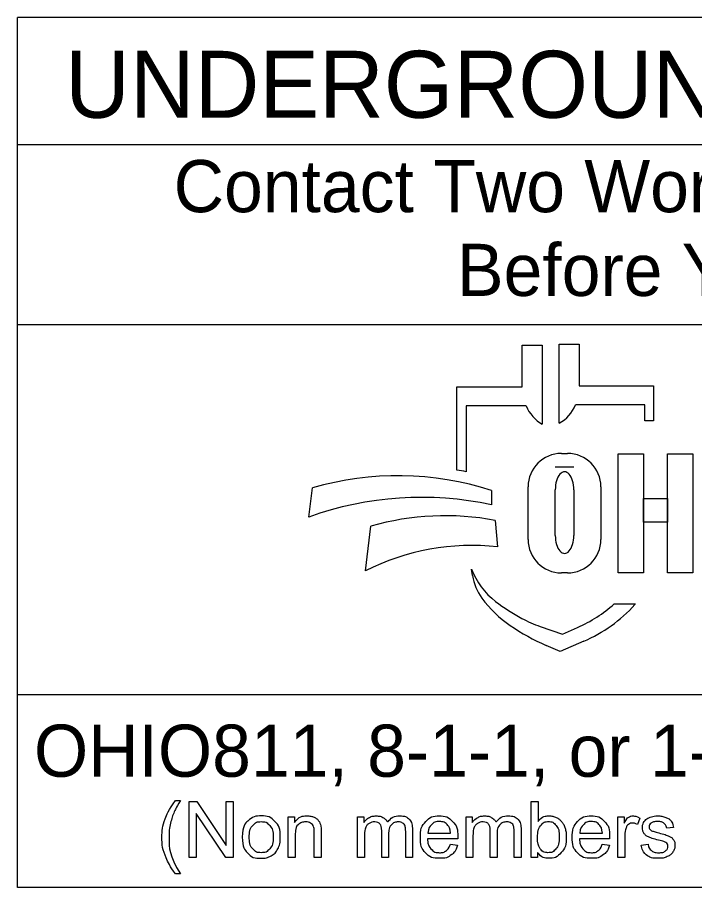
# Model space of a CAD drawing. Extents: x -10.1 to 68, y -9.5 to 29.2.
# Drawn here: x 2.978 to 4.796, y 2.143 to 4.48 of the extents above; entities that cross this region are included whole.
import ezdxf

# ---------------------------------------------------------------- set-up
doc = ezdxf.new("R2010")
doc.units = 0
doc.layers.add('SH_Data', color=7, linetype='Continuous')
doc.layers.add('SH_Text', color=7, linetype='Continuous')

msp = doc.modelspace()

# ---------------------------------------------------------------- linework, layer by layer
at = {"layer": 'SH_Data'}
for p, q in [((2.9775, 2.1428), (2.9775, 4.4803)), ((7.2275, 4.4803), (2.9775, 4.4803)), ((2.9775, 4.1387), (7.2275, 4.1387)), ((2.9775, 3.6553), (7.2275, 3.6553)), ((7.2275, 2.6607), (2.9775, 2.6607)), ((7.2275, 2.1428), (2.9775, 2.1428))]:
    msp.add_line(p, q, dxfattribs=at)
at = {"layer": 'SH_Text'}
for p, q in [((4.3335, 3.4883), (4.3335, 3.5998)), ((4.3335, 3.5998), (4.3872, 3.5998)), ((4.3872, 3.5998), (4.3872, 3.3877)), ((4.4329, 3.39), (4.4329, 3.6021)), ((4.4329, 3.6021), (4.4865, 3.6021)), ((4.4865, 3.6021), (4.4865, 3.4906)), ((4.1576, 3.2644), (4.1576, 3.4883)), ((4.1576, 3.4883), (4.3335, 3.4883)), ((4.4865, 3.4906), (4.6857, 3.4906)), ((4.6857, 3.4906), (4.6857, 3.3968)), ((4.1828, 3.4369), (4.1828, 3.26)), ((4.3439, 3.4369), (4.1828, 3.4369)), ((4.6625, 3.4392), (4.4761, 3.4392)), ((4.6625, 3.3968), (4.6625, 3.4392)), ((4.6857, 3.3968), (4.6625, 3.3968)), ((4.4385, 3.3091), (4.4551, 3.3091)), ((4.4718, 3.2721), (4.422, 3.2721)), ((3.7602, 3.1381), (3.7696, 3.2162)), ((4.2509, 3.2097), (4.2509, 3.1709)), ((4.3491, 3.0776), (4.3491, 3.2196)), ((4.422, 3.089), (4.422, 3.2114)), ((4.4718, 3.2114), (4.4718, 3.089)), ((4.5445, 3.2196), (4.5445, 3.0776)), ((3.912, 2.9936), (3.9267, 3.1137)), ((4.2608, 3.1291), (4.2671, 3.0582)), ((4.1997, 2.9807), (4.1967, 2.9986)), ((4.4551, 2.9882), (4.4385, 2.9882)), ((4.58, 2.9048), (4.6375, 2.9048)), ((4.3816, 2.8444), (4.441, 2.8239)), ((4.441, 2.8239), (4.4821, 2.8417)), ((4.435, 2.7769), (4.3976, 2.7934)), ((4.4983, 2.8044), (4.435, 2.7769))]:
    msp.add_line(p, q, dxfattribs=at)
for points in [[(4.591, 3.3081), (4.6589, 3.3081), (4.6589, 2.9881), (4.591, 2.9881)], [(4.7231, 3.3081), (4.7911, 3.3081), (4.7911, 2.9881), (4.7231, 2.9881)], [(4.6589, 3.1882), (4.7231, 3.1882), (4.7231, 3.1242), (4.6589, 3.1242)]]:
    msp.add_lwpolyline(points, close=True, dxfattribs=at)
for points in [[(3.4021, 2.3766), (3.4153, 2.3766)], [(3.4389, 2.2239), (3.4389, 2.3741), (3.4592, 2.3741), (3.5382, 2.2561), (3.5382, 2.3741), (3.5572, 2.3741), (3.5572, 2.2239), (3.5369, 2.2239), (3.4579, 2.3419), (3.4579, 2.2239), (3.4389, 2.2239)], [(4.3743, 2.2239), (4.3573, 2.2239), (4.3573, 2.3741), (4.3757, 2.3741), (4.3757, 2.3206)], [(3.7048, 2.2239), (3.7048, 2.3328), (3.7214, 2.3328), (3.7214, 2.3173)], [(3.8912, 2.2239), (3.8912, 2.3328), (3.9077, 2.3328), (3.9077, 2.3174)], [(4.1826, 2.2239), (4.1826, 2.3328), (4.1991, 2.3328), (4.1991, 2.3174)], [(4.5904, 2.2239), (4.5904, 2.3328), (4.607, 2.3328), (4.607, 2.3163)], [(4.6495, 2.3293), (4.643, 2.3122)], [(3.7932, 2.2908), (3.7932, 2.2239), (3.7748, 2.2239), (3.7748, 2.2901)], [(3.9743, 2.2871), (3.9743, 2.2239), (3.9559, 2.2239), (3.9559, 2.2946)], [(4.0388, 2.2986), (4.0388, 2.2239), (4.0203, 2.2239), (4.0203, 2.2924)], [(4.2657, 2.2871), (4.2657, 2.2239), (4.2473, 2.2239), (4.2473, 2.2946)], [(4.3301, 2.2986), (4.3301, 2.2239), (4.3117, 2.2239), (4.3117, 2.2924)], [(4.7394, 2.3046), (4.7213, 2.3022)], [(3.7233, 2.2833), (3.7233, 2.2239), (3.7048, 2.2239)], [(3.9097, 2.2803), (3.9097, 2.2239), (3.8912, 2.2239)], [(4.16, 2.2736), (4.0788, 2.2736)], [(4.0799, 2.2887), (4.1406, 2.2887)], [(4.201, 2.2803), (4.201, 2.2239), (4.1826, 2.2239)], [(4.568, 2.2736), (4.4868, 2.2736)], [(4.4879, 2.2887), (4.5486, 2.2887)], [(4.6088, 2.2809), (4.6088, 2.2239), (4.5904, 2.2239)], [(4.1404, 2.2591), (4.1595, 2.2567)], [(4.5484, 2.2591), (4.5675, 2.2567)], [(4.653, 2.2564), (4.6712, 2.2593)], [(4.3743, 2.2375), (4.3743, 2.2239)], [(3.4153, 2.1798), (3.4021, 2.1798)]]:
    msp.add_lwpolyline(points, dxfattribs=at)
for centre, radius, start, end in [((4.4353, 3.4736), 0.0985, 201.9296, 240.7469), ((4.3847, 3.476), 0.0985, 299.2531, 338.0704), ((4.4385, 3.2196), 0.0895, 90, 180), ((4.4551, 3.2196), 0.0895, 0, 90), ((3.9997, 2.4302), 0.8191, 72.1402, 106.3144), ((4.0295, 2.4554), 0.8191, 79.2074, 81.0007), ((4.0628, 2.2991), 0.8919, 77.8238, 109.8274), ((4.1267, 2.4094), 0.7322, 79.44, 105.8467), ((4.4385, 3.0776), 0.0895, 180, 270), ((4.4551, 3.0776), 0.0895, 270, 0), ((4.1987, 2.4262), 0.6357, 83.8248, 116.8021), ((4.3841, 3.0707), 0.2008, 201.0457, 232.5314), ((4.341, 3.0048), 0.1433, 189.6817, 216.0884), ((4.4747, 3.1022), 0.3088, 216.0884, 235.7167), ((4.5766, 3.3219), 0.5173, 232.5314, 241.794), ((4.3387, 3.1722), 0.3602, 293.4582, 312.0712), ((4.3387, 3.1722), 0.401, 293.4582, 317.8286), ((4.4914, 3.1631), 0.3371, 241.794, 250.9821), ((4.6412, 3.3465), 0.6044, 235.7167, 246.2325)]:
    msp.add_arc(centre, radius, start, end, dxfattribs=at)
for centre, start_param, end_param in [((4.4469, 3.2114), 4.712389, 7.853982), ((4.4469, 3.089), 1.570796, 4.712389)]:
    msp.add_ellipse(centre, major_axis=(0, 0.0484), ratio=0.514403, start_param=start_param, end_param=end_param, dxfattribs=at)
for points in [[(3.4021, 2.1798), (3.3869, 2.199), (3.3763, 2.2248), (3.3657, 2.2506), (3.3657, 2.2783), (3.3657, 2.3026), (3.3736, 2.325), (3.3829, 2.3509), (3.4021, 2.3766)], [(3.4153, 2.3766), (3.4029, 2.3553), (3.3989, 2.3462), (3.3927, 2.332), (3.3891, 2.3167), (3.3847, 2.2975), (3.3847, 2.2782), (3.3847, 2.2289), (3.4153, 2.1798)], [(3.5814, 2.2783), (3.5814, 2.3085), (3.5981, 2.3231), (3.6122, 2.3352), (3.6323, 2.3352), (3.6547, 2.3352), (3.669, 2.3205), (3.6832, 2.3058), (3.6832, 2.2799), (3.6832, 2.2589), (3.6769, 2.2469), (3.6706, 2.2348), (3.6586, 2.2282), (3.6466, 2.2215), (3.6323, 2.2215), (3.6095, 2.2215), (3.5954, 2.2362), (3.5814, 2.2508), (3.5814, 2.2783)], [(3.6003, 2.2783), (3.6003, 2.2574), (3.6094, 2.247), (3.6185, 2.2366), (3.6323, 2.2366), (3.646, 2.2366), (3.6551, 2.2471), (3.6642, 2.2575), (3.6642, 2.279), (3.6642, 2.2991), (3.6551, 2.3095), (3.6459, 2.3199), (3.6323, 2.3199), (3.6185, 2.3199), (3.6094, 2.3096), (3.6003, 2.2992), (3.6003, 2.2783)], [(3.7214, 2.3173), (3.7334, 2.3352), (3.756, 2.3352), (3.7659, 2.3352), (3.7741, 2.3316), (3.7823, 2.3281), (3.7864, 2.3224), (3.7905, 2.3166), (3.7922, 2.3087), (3.7932, 2.3036), (3.7932, 2.2908)], [(3.7748, 2.2901), (3.7748, 2.3013), (3.7726, 2.3069), (3.7705, 2.3125), (3.765, 2.3158), (3.7595, 2.3191), (3.7521, 2.3191), (3.7404, 2.3191), (3.7318, 2.3117), (3.7233, 2.3042), (3.7233, 2.2833)], [(3.9077, 2.3174), (3.9128, 2.3254), (3.9214, 2.3303), (3.9299, 2.3352), (3.9407, 2.3352), (3.9528, 2.3352), (3.9606, 2.3301), (3.9683, 2.3251), (3.9715, 2.3161), (3.9844, 2.3352), (4.0051, 2.3352), (4.0213, 2.3352), (4.03, 2.3262), (4.0388, 2.3172), (4.0388, 2.2986)], [(3.9559, 2.2946), (3.9559, 2.3069), (3.9514, 2.313), (3.9469, 2.3191), (3.9366, 2.3191), (3.9288, 2.3191), (3.9222, 2.315), (3.9156, 2.311), (3.9126, 2.3031), (3.9097, 2.2952), (3.9097, 2.2803)], [(4.0203, 2.2924), (4.0203, 2.3035), (4.0185, 2.3083), (4.0168, 2.3132), (4.012, 2.3162), (4.0073, 2.3191), (4.001, 2.3191), (3.9895, 2.3191), (3.9819, 2.3115), (3.9743, 2.3039), (3.9743, 2.2871)], [(4.1595, 2.2567), (4.155, 2.24), (4.1428, 2.2307), (4.1306, 2.2215), (4.1117, 2.2215), (4.0878, 2.2215), (4.0738, 2.2362), (4.0598, 2.2509), (4.0598, 2.2774), (4.0598, 2.3049), (4.074, 2.32), (4.0881, 2.3352), (4.1106, 2.3352), (4.1324, 2.3352), (4.1463, 2.3203), (4.1601, 2.3055), (4.1601, 2.2785), (4.1601, 2.2769), (4.16, 2.2736)], [(4.1406, 2.2887), (4.1394, 2.3025), (4.1337, 2.3094), (4.1249, 2.3201), (4.1108, 2.3201), (4.0981, 2.3201), (4.0894, 2.3115), (4.0808, 2.303), (4.0799, 2.2887)], [(4.1991, 2.3174), (4.2042, 2.3254), (4.2127, 2.3303), (4.2212, 2.3352), (4.2321, 2.3352), (4.2442, 2.3352), (4.2519, 2.3301), (4.2597, 2.3251), (4.2628, 2.3161), (4.2758, 2.3352), (4.2965, 2.3352), (4.3127, 2.3352), (4.3214, 2.3262), (4.3301, 2.3172), (4.3301, 2.2986)], [(4.2473, 2.2946), (4.2473, 2.3069), (4.2428, 2.313), (4.2383, 2.3191), (4.228, 2.3191), (4.2202, 2.3191), (4.2136, 2.315), (4.207, 2.311), (4.204, 2.3031), (4.201, 2.2952), (4.201, 2.2803)], [(4.3117, 2.2924), (4.3117, 2.3035), (4.3099, 2.3083), (4.3081, 2.3132), (4.3034, 2.3162), (4.2987, 2.3191), (4.2923, 2.3191), (4.2809, 2.3191), (4.2733, 2.3115), (4.2657, 2.3039), (4.2657, 2.2871)], [(4.3741, 2.2792), (4.3741, 2.2596), (4.3794, 2.2509), (4.3881, 2.2366), (4.4029, 2.2366), (4.415, 2.2366), (4.4238, 2.2471), (4.4326, 2.2576), (4.4326, 2.2784), (4.4326, 2.2998), (4.4241, 2.3099), (4.4157, 2.3201), (4.4038, 2.3201), (4.3917, 2.3201), (4.3829, 2.3096), (4.3741, 2.299), (4.3741, 2.2792)], [(4.3757, 2.3206), (4.3874, 2.3352), (4.4055, 2.3352), (4.4155, 2.3352), (4.4245, 2.3311), (4.4335, 2.3271), (4.4392, 2.3198), (4.445, 2.3124), (4.4483, 2.3021), (4.4516, 2.2918), (4.4516, 2.28), (4.4516, 2.252), (4.4378, 2.2368), (4.4239, 2.2215), (4.4046, 2.2215), (4.3853, 2.2215), (4.3743, 2.2375)], [(4.5675, 2.2567), (4.563, 2.24), (4.5508, 2.2307), (4.5386, 2.2215), (4.5196, 2.2215), (4.4958, 2.2215), (4.4818, 2.2362), (4.4678, 2.2509), (4.4678, 2.2774), (4.4678, 2.3049), (4.482, 2.32), (4.4961, 2.3352), (4.5186, 2.3352), (4.5404, 2.3352), (4.5543, 2.3203), (4.5681, 2.3055), (4.5681, 2.2785), (4.5681, 2.2769), (4.568, 2.2736)], [(4.5486, 2.2887), (4.5474, 2.3025), (4.5417, 2.3094), (4.5328, 2.3201), (4.5188, 2.3201), (4.5061, 2.3201), (4.4974, 2.3115), (4.4888, 2.303), (4.4879, 2.2887)], [(4.607, 2.3163), (4.6133, 2.3278), (4.6187, 2.3315), (4.6241, 2.3352), (4.6305, 2.3352), (4.6398, 2.3352), (4.6495, 2.3293)], [(4.643, 2.3122), (4.6363, 2.3162), (4.6295, 2.3162), (4.6235, 2.3162), (4.6187, 2.3125), (4.6139, 2.3089), (4.6119, 2.3024), (4.6088, 2.2926), (4.6088, 2.2809)], [(4.7213, 2.3022), (4.7201, 2.3106), (4.7142, 2.3153), (4.7083, 2.3201), (4.6975, 2.3201), (4.6848, 2.3201), (4.6794, 2.3159), (4.6739, 2.3116), (4.6739, 2.306), (4.6739, 2.3024), (4.6762, 2.2995), (4.6785, 2.2966), (4.6833, 2.2946), (4.686, 2.2936), (4.6996, 2.2899), (4.7192, 2.2847), (4.7269, 2.2813), (4.7347, 2.278), (4.7391, 2.2717), (4.7435, 2.2653), (4.7435, 2.2559), (4.7435, 2.2467), (4.7381, 2.2386), (4.7327, 2.2304), (4.7226, 2.226), (4.7124, 2.2215), (4.6996, 2.2215), (4.6784, 2.2215), (4.6672, 2.2303), (4.6561, 2.2391), (4.653, 2.2564)], [(4.6712, 2.2593), (4.6727, 2.2483), (4.6798, 2.2425), (4.6868, 2.2366), (4.6995, 2.2366), (4.7122, 2.2366), (4.7184, 2.2418), (4.7245, 2.247), (4.7245, 2.254), (4.7245, 2.2602), (4.7191, 2.2638), (4.7153, 2.2663), (4.7002, 2.2701), (4.6799, 2.2752), (4.672, 2.2789), (4.6642, 2.2827), (4.6601, 2.2893), (4.6561, 2.2959), (4.6561, 2.3038), (4.6561, 2.3111), (4.6594, 2.3173), (4.6628, 2.3235), (4.6685, 2.3276), (4.6728, 2.3308), (4.6803, 2.333), (4.6877, 2.3352), (4.6962, 2.3352), (4.709, 2.3352), (4.7187, 2.3315), (4.7284, 2.3278), (4.733, 2.3215), (4.7377, 2.3152), (4.7394, 2.3046)], [(4.0788, 2.2736), (4.0799, 2.2557), (4.089, 2.2462), (4.0981, 2.2366), (4.1117, 2.2366), (4.1219, 2.2366), (4.1291, 2.242), (4.1362, 2.2473), (4.1404, 2.2591)], [(4.4868, 2.2736), (4.4879, 2.2557), (4.497, 2.2462), (4.5061, 2.2366), (4.5197, 2.2366), (4.5299, 2.2366), (4.537, 2.242), (4.5442, 2.2473), (4.5484, 2.2591)]]:
    msp.add_open_spline(points, degree=3, dxfattribs=at)

# ---------------------------------------------------------------- texts
for s, height, p in [('UNDERGROUND UTILITIES', 0.18, (3.1057, 4.2106)), ('Contact Two Working Days', 0.14, (3.3972, 3.9571)), ('Before You Dig', 0.14, (4.1583, 3.7321)), ('OHIO811, 8-1-1, or 1-800-362-2764', 0.14, (3.022, 2.4406))]:
    msp.add_text(s, height=height, dxfattribs=at).set_placement(p)

doc.saveas('drawing.dxf')
